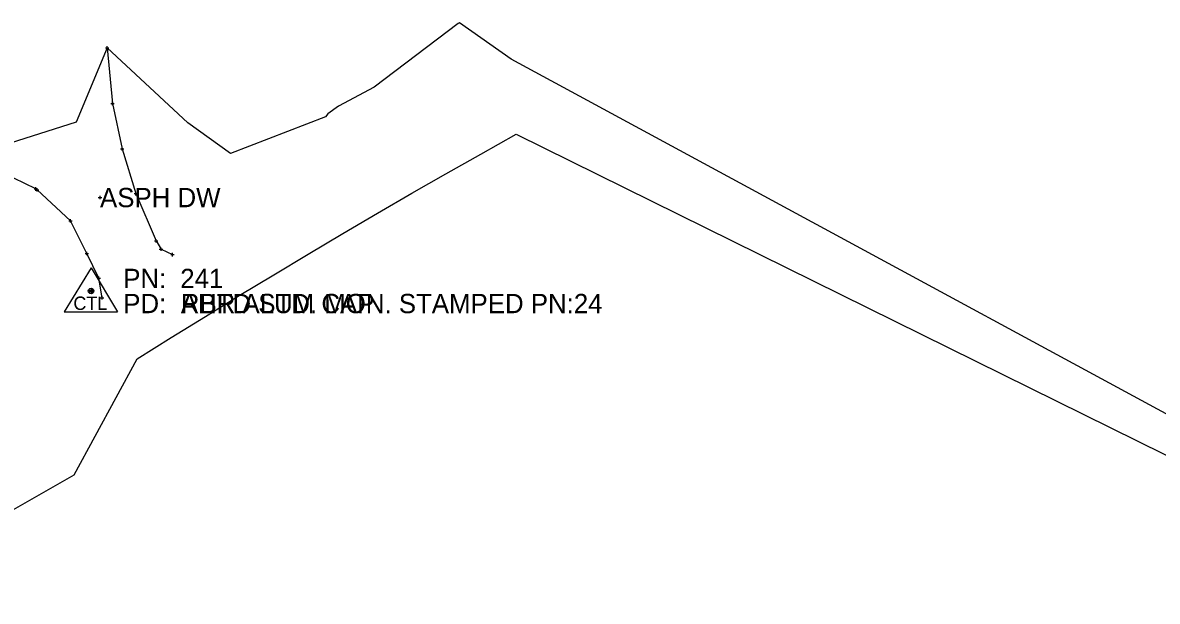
# Model space of a CAD drawing. Extents: x -1 to 1157254, y -1 to 2021979.
# Drawn here: x 1151070 to 1151493.1, y 2020061.5 to 2020277.4 of the extents above; entities that cross this region are included whole.
import ezdxf

# ---------------------------------------------------------------- set-up
doc = ezdxf.new("R2010")
doc.units = 0
for name, color, linetype in [('S_AREA_CALC', 7, 'Continuous'), ('S_BUILDING_ANNOT', 7, 'Continuous'), ('S_EDGE_PAVEMENT_ANNOT', 7, 'Continuous'), ('S_ENV_CONSTRAINT', 7, 'Continuous'), ('S_GAS_PUMP_ISLAND_ANNOT', 7, 'Continuous'), ('S_GAS_UTILITIES', 7, 'Continuous'), ('S_GATE', 7, 'Continuous')]:
    doc.layers.add(name, color=color, linetype=linetype)

msp = doc.modelspace()

# ---------------------------------------------------------------- linework, layer by layer
at = {"layer": 'S_AREA_CALC'}
for p, q in [((1151095.48, 2020185.96), (1151085.45, 2020169.45)), ((1151095.49, 2020185.96), (1151085.46, 2020169.45)), ((1151095.48, 2020185.96), (1151105.3, 2020169.45)), ((1151095.49, 2020185.96), (1151105.31, 2020169.45)), ((1151085.45, 2020169.45), (1151105.3, 2020169.45)), ((1151085.46, 2020169.45), (1151105.31, 2020169.45))]:
    msp.add_line(p, q, dxfattribs=at)
for centre, radius in [((1151095.49, 2020177.26), 1.04), ((1151095.48, 2020177.26), 1.04), ((1151095.49, 2020177.26), 0.609), ((1151095.48, 2020177.26), 0.609), ((1151095.49, 2020177.26), 0.344), ((1151095.48, 2020177.26), 0.344)]:
    msp.add_circle(centre, radius, dxfattribs=at)
at = {"layer": 'S_BUILDING_ANNOT'}
for p, q in [((1151100.83, 2020267.93), (1151102.11, 2020267.93)), ((1151101.47, 2020267.29), (1151101.47, 2020268.56)), ((1151101.47, 2020267.93), (1151101.47, 2020267.93)), ((1151103.49, 2020246.55), (1151103.49, 2020247.82)), ((1151102.85, 2020247.18), (1151104.12, 2020247.19)), ((1151103.49, 2020247.19), (1151103.49, 2020247.19)), ((1151107.05, 2020229.71), (1151107.05, 2020230.98)), ((1151106.41, 2020230.34), (1151107.69, 2020230.35)), ((1151107.05, 2020230.34), (1151107.05, 2020230.34)), ((1151074.25, 2020215.32), (1151075.52, 2020215.32)), ((1151074.77, 2020215.02), (1151076.04, 2020215.02)), ((1151074.89, 2020214.69), (1151074.88, 2020215.96)), ((1151074.88, 2020215.32), (1151074.88, 2020215.32)), ((1151075.4, 2020214.38), (1151075.4, 2020215.66)), ((1151075.4, 2020215.02), (1151075.4, 2020215.02)), ((1151112.21, 2020212.95), (1151112.21, 2020214.22)), ((1151098.19, 2020212.12), (1151099.46, 2020212.12)), ((1151098.83, 2020211.49), (1151098.83, 2020212.76)), ((1151098.83, 2020212.12), (1151098.83, 2020212.12)), ((1151111.57, 2020213.58), (1151112.85, 2020213.58)), ((1151112.21, 2020213.58), (1151112.21, 2020213.58)), ((1151087.22, 2020203.41), (1151088.49, 2020203.41)), ((1151087.86, 2020202.78), (1151087.85, 2020204.05)), ((1151087.85, 2020203.41), (1151087.85, 2020203.41)), ((1151119.1, 2020195.99), (1151120.38, 2020195.99)), ((1151119.74, 2020195.35), (1151119.74, 2020196.63)), ((1151119.74, 2020195.99), (1151119.74, 2020195.99)), ((1151120.93, 2020192.92), (1151122.2, 2020192.92)), ((1151121.57, 2020192.29), (1151121.56, 2020193.56)), ((1151121.57, 2020192.92), (1151121.57, 2020192.92)), ((1151093.29, 2020191.21), (1151094.57, 2020191.21)), ((1151093.93, 2020190.58), (1151093.93, 2020191.85)), ((1151093.93, 2020191.21), (1151093.93, 2020191.21)), ((1151125.25, 2020190.83), (1151126.52, 2020190.83)), ((1151125.88, 2020190.19), (1151125.88, 2020191.46)), ((1151125.88, 2020190.83), (1151125.88, 2020190.83)), ((1151097.76, 2020182.07), (1151099.03, 2020182.07)), ((1151098.4, 2020181.43), (1151098.39, 2020182.7)), ((1151098.4, 2020182.07), (1151098.4, 2020182.07)), ((1151098.95, 2020174.74), (1151100.22, 2020174.74)), ((1151099.58, 2020174.1), (1151099.58, 2020175.37)), ((1151099.58, 2020174.74), (1151099.58, 2020174.74))]:
    msp.add_line(p, q, dxfattribs=at)
at = {"layer": 'S_EDGE_PAVEMENT_ANNOT'}
for points in [[(1151101.47, 2020267.93), (1151103.49, 2020247.19), (1151107.05, 2020230.34), (1151112.21, 2020213.58), (1151119.74, 2020195.99), (1151121.57, 2020192.92), (1151125.88, 2020190.83)], [(1151074.88, 2020215.32), (1151062.61, 2020221.34), (1151042.62, 2020221.57), (1151018.13, 2020217.51), (1150992.22, 2020211.95)]]:
    msp.add_lwpolyline(points, dxfattribs=at)
at = {"layer": 'S_ENV_CONSTRAINT'}
msp.add_lwpolyline([(1151099.58, 2020174.74), (1151098.4, 2020182.07), (1151093.93, 2020191.21), (1151087.85, 2020203.41), (1151075.4, 2020215.02)], dxfattribs=at)
at = {"layer": 'S_GAS_PUMP_ISLAND_ANNOT'}
for points in [[(1151607.12, 2020071.45), (1151252.22, 2020263.8), (1151232.95, 2020277.37), (1151232.67, 2020277.18), (1151232.42, 2020277.01), (1151201.03, 2020253.32), (1151187.74, 2020246.24), (1151183.73, 2020243.4), (1151182.93, 2020242.29), (1151147.53, 2020228.59), (1151131.6, 2020240), (1151101.47, 2020267.93), (1151089.92, 2020240.24), (1151065.37, 2020232.37)], [(1151051.63, 2020087.24), (1151089.17, 2020108.61), (1151112.63, 2020152), (1151125.38, 2020159.91), (1151138.14, 2020167.8), (1151150.75, 2020175.58), (1151163.6, 2020183.34), (1151176.46, 2020191.05), (1151189.33, 2020198.67), (1151202.27, 2020206.25), (1151215.17, 2020213.74), (1151227.84, 2020220.95), (1151240.89, 2020228.36), (1151254.04, 2020235.81), (1151606.65, 2020061.47)]]:
    msp.add_lwpolyline(points, dxfattribs=at)

# ---------------------------------------------------------------- texts
at = {"layer": 'S_AREA_CALC'}
msp.add_text('CTL', height=4.998, dxfattribs=at).set_placement((1151088.9, 2020170.19))
msp.add_text('CTL', height=4.998, dxfattribs=at).set_placement((1151088.9, 2020170.19))
at = {"layer": 'S_GAS_UTILITIES'}
for s, p in [('PN: ', (1151107.48, 2020178.34)), ('PN: ', (1151107.49, 2020178.34)), ('241', (1151128.75, 2020178.34)), ('24', (1151128.75, 2020178.34)), ('PD: ', (1151107.48, 2020168.98)), ('PD: ', (1151107.49, 2020168.98)), ('AHTD STD. MON. STAMPED PN:24', (1151128.96, 2020168.98)), ('RBR ALUM CAP', (1151128.96, 2020168.98))]:
    msp.add_text(s, height=7.2, dxfattribs=at).set_placement(p)
at = {"layer": 'S_GATE'}
msp.add_text('ASPH DW', height=7.2, dxfattribs=at).set_placement((1151098.83, 2020208.52))

doc.saveas('drawing.dxf')
